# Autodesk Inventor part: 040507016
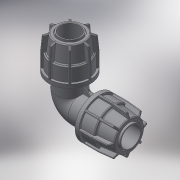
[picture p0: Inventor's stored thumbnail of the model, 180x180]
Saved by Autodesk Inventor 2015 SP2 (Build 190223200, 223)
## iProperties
Created: 2017-08
Part Number: 040507016
Material: Generic
Description: PLASSON IRRIFIT ELBOW 16-16
Document SubType Name: Modeling
Designer: KIM
Density: 1 g/cm^3
Appearance: Default
Author: KIM
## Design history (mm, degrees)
derived "040507.ipt"
feature "Solid1::040507.ipt"
tag "TaggingFeature1"
body "Solid1"
other parameters: "d5" = 28.8, "d6" = 14.4, "d10" = 34, "d22" = 22.4, "d24" = 3.2, "d25" = 30.6, "d26" = 27.2, "d31" = 0.8, "d49" = 1.7, "d50" = 0, "d58" = 0.48, "d61" = 360 deg, "d77" = 16, "d78" = 6 deg, "d80" = 17.6, "d82" = 2.4, "d84" = 5 deg, "d85" = 70 deg, "d86" = 32.3, "d87" = 0.8, "d88" = 0, "d89" = 28.9, "d90" = 8, "d91" = 0, "d93" = 90 deg, "d102" = 12.8, "d103" = 12.8, "d104" = 0.8, "d105" = 0, "d_" = 16, "E_" = 34, "l_" = 16
